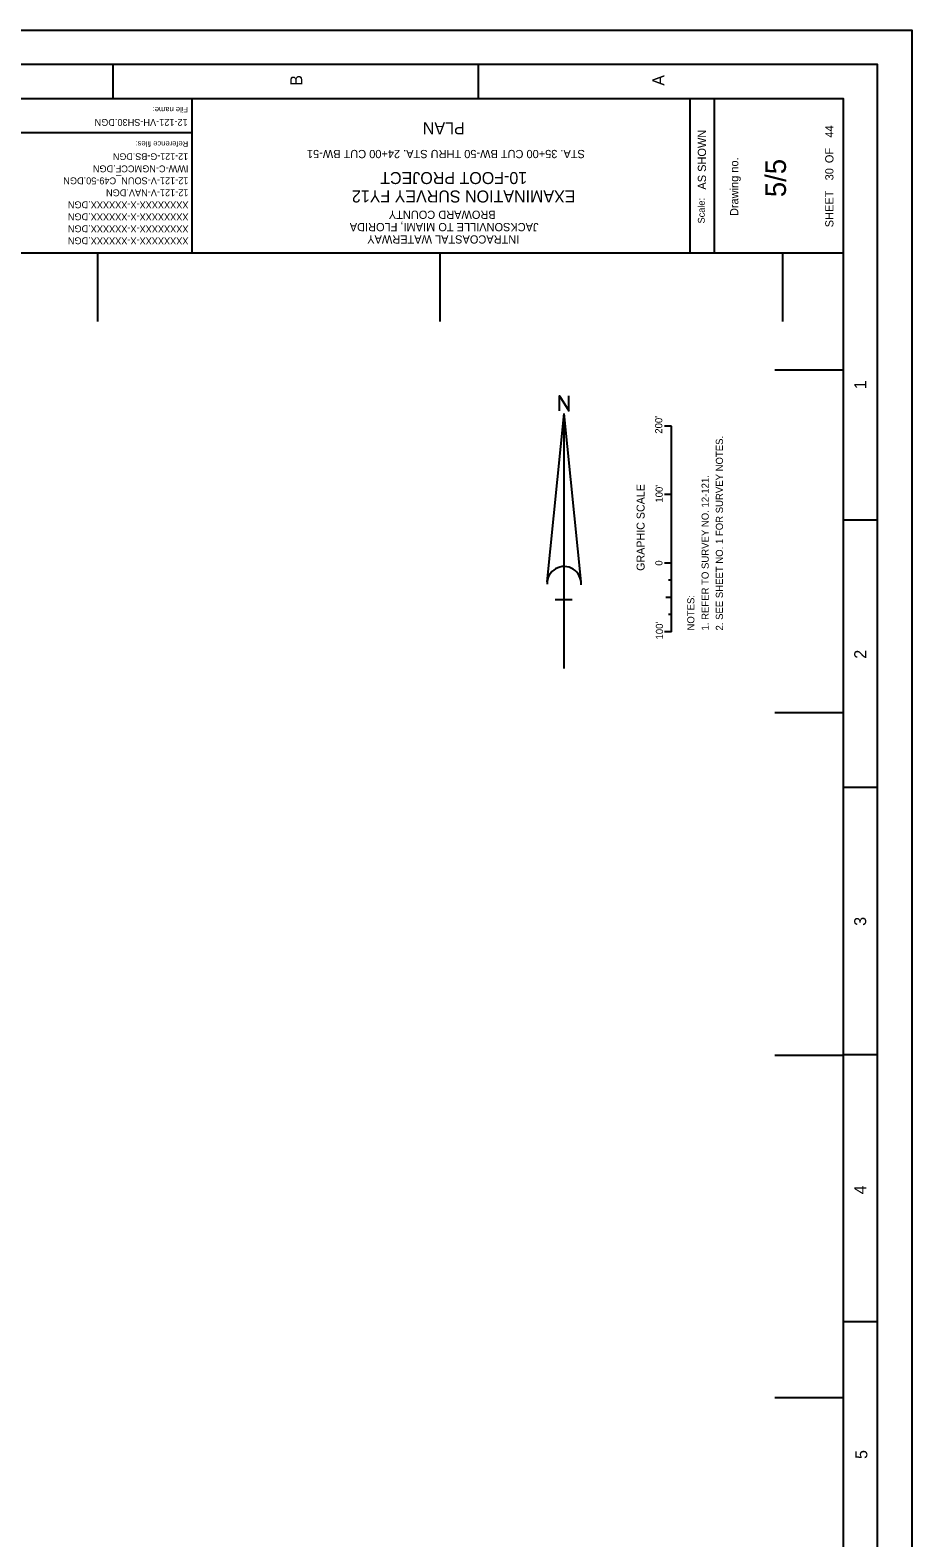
# Model space of a CAD drawing. Extents: x 945289 to 948688, y 635096 to 639496.
# Drawn here: x 947401 to 948688, y 637296 to 639496 of the extents above; entities that cross this region are included whole.
import ezdxf

# ---------------------------------------------------------------- set-up
doc = ezdxf.new("R2010")
doc.units = 0
for name, color, linetype in [('G-ANNO-NPLT', 7, 'Continuous'), ('G-ANNO-TEXT-DRWG', 7, 'Continuous'), ('G-ANNO-TEXT-PROJ', 7, 'Continuous'), ('G-ANNO-TEXT-TTLB', 7, 'Continuous'), ('G-ANNO-TTLB', 7, 'Continuous'), ('V-ANNO-NOTE', 7, 'Continuous'), ('V-ANNO-SYMB', 7, 'Continuous'), ('V-TOPO-COOR-STAT', 7, 'Continuous')]:
    doc.layers.add(name, color=color, linetype=linetype)

msp = doc.modelspace()

# ---------------------------------------------------------------- linework, layer by layer
at = {"layer": 'G-ANNO-NPLT'}
msp.add_lwpolyline([(945288.5, 635095.9), (945288.5, 639495.8), (948688.5, 639495.8), (948688.5, 635095.9)], close=True, dxfattribs=at)
msp.add_lwpolyline([(948638.5, 639496), (948688.5, 639496), (948688.5, 639446)], dxfattribs=at)
at = {"layer": 'G-ANNO-TTLB'}
for p, q in [((947521.9, 639445.8), (947521.9, 639395.8)), ((948055.2, 639445.8), (948055.2, 639395.8)), ((947637.7, 639170.8), (947637.7, 639395.8)), ((948364.7, 639170.8), (948364.7, 639395.8)), ((948400.4, 639170.8), (948400.4, 639395.8)), ((947286.3, 639346.5), (947637.7, 639346.5)), ((945388.5, 639170.8), (948588.5, 639170.8)), ((948638.5, 638780.8), (948588.5, 638780.8)), ((948638.5, 638390.8), (948588.5, 638390.8)), ((948638.5, 638000.8), (948588.5, 638000.8)), ((948638.5, 637610.9), (948588.5, 637610.9))]:
    msp.add_line(p, q, dxfattribs=at)
for points in [[(948638.5, 635145.9), (948638.5, 639445.8), (945338.5, 639445.8), (945338.5, 635145.9)], [(945388.5, 639395.8), (945388.5, 635270.9), (948588.5, 635270.9), (948588.5, 639395.8)]]:
    msp.add_lwpolyline(points, close=True, dxfattribs=at)
at = {"layer": 'V-ANNO-NOTE'}
for p, q in [((948337.8, 638918.2), (948327.3, 638918.2)), ((948337.8, 638618.2), (948337.8, 638918.2)), ((948337.8, 638818.2), (948327.3, 638818.2)), ((948337.8, 638718.2), (948327.3, 638718.2)), ((948337.8, 638718.2), (948327.3, 638718.2)), ((948337.8, 638718.2), (948332.8, 638718.2)), ((948337.8, 638693.2), (948333, 638693.2)), ((948337.8, 638668.2), (948329.3, 638668.2)), ((948337.8, 638643.2), (948333, 638643.2)), ((948337.8, 638618.2), (948327.3, 638618.2))]:
    msp.add_line(p, q, dxfattribs=at)
at = {"layer": 'V-ANNO-SYMB'}
for p, q in [((948156.1, 638690.9), (948180.8, 638936.7)), ((948180.8, 638564.3), (948180.8, 638936.7)), ((948205.5, 638690.9), (948180.8, 638936.7)), ((948192.6, 638664.9), (948167.8, 638664.9))]:
    msp.add_line(p, q, dxfattribs=at)
msp.add_lwpolyline([(948173.9, 638940.7), (948173.9, 638962.4), (948187.5, 638940.7), (948187.5, 638962.4)], dxfattribs=at)
msp.add_arc((948180.8, 638688.5), 24.8, 355.2984, 182.0673, dxfattribs=at)
at = {"layer": 'V-TOPO-COOR-STAT'}
for p, q in [((947500, 639070.8), (947500, 639170.8)), ((948000, 639070.8), (948000, 639170.8)), ((948500, 639070.8), (948500, 639170.8)), ((948588.5, 639000), (948488.5, 639000)), ((948588.5, 638500), (948488.5, 638500)), ((948588.5, 638000), (948488.5, 638000)), ((948588.5, 637500), (948488.5, 637500))]:
    msp.add_line(p, q, dxfattribs=at)

# ---------------------------------------------------------------- texts
at = {"layer": 'G-ANNO-TEXT-DRWG'}
for s, height, rotation, p in [('12-121-VH-SH30.DGN', 10, 180, (947631.3, 639366.3)), ('PLAN', 17.5, 180, (948035.7, 639361.4)), (' 30          44', 12, 90, (948574, 639272.3)), ('STA. 35+00 CUT BW-50 THRU STA. 24+00 CUT BW-51', 12, 180, (948211.1, 639321.2)), ('IWW-C-NGMCCF.DGN', 10, 180, (947632.4, 639298.6)), ('5/5', 30, 90, (948504.7, 639252.3)), ('12-121-V-SOUN_C49-50.DGN', 10, 180, (947632.4, 639281.1)), ('12-121-V-NAV.DGN', 10, 180, (947632.4, 639263.6)), ('XXXXXXXX-X-XXXXXX.DGN', 10, 180, (947632.4, 639246.1)), ('XXXXXXXX-X-XXXXXX.DGN', 10, 180, (947632.4, 639228.6)), ('XXXXXXXX-X-XXXXXX.DGN', 10, 180, (947632.4, 639211.1)), ('XXXXXXXX-X-XXXXXX.DGN', 10, 180, (947632.4, 639193.6))]:
    msp.add_text(s, height=height, rotation=rotation, dxfattribs=at).set_placement(p)
at = {"layer": 'G-ANNO-TEXT-PROJ'}
for s, height, p in [('12-121-G-BS.DGN', 9.8, (947632, 639316.3)), ('10-FOOT PROJECT', 17.5, (948126.9, 639288.9)), ('EXAMINATION SURVEY FY12', 17.5, (948197.4, 639262)), ('BROWARD COUNTY', 12, (948080.9, 639232.6)), ('JACKSONVILLE TO MIAMI, FLORIDA', 12, (948143.4, 639214.6)), ('INTRACOASTAL WATERWAY', 12, (948115.4, 639196.6))]:
    msp.add_text(s, height=height, rotation=180, dxfattribs=at).set_placement(p)
at = {"layer": 'G-ANNO-TEXT-TTLB'}
for s, height, rotation, p in [('File name:', 8, 180, (947631.7, 639383.9)), ('AS SHOWN', 12, 90, (948388, 639263.3)), ('Reference files:', 8, 180, (947631.9, 639333.9)), ('SHEET         OF', 12, 90, (948574, 639208.3)), ('Drawing no.', 12, 90, (948435.1, 639224.7)), ('Scale:', 10, 90, (948386.1, 639213.9))]:
    msp.add_text(s, height=height, rotation=rotation, dxfattribs=at).set_placement(p)
at = {"layer": 'G-ANNO-TTLB'}
for s, p in [('B', (947798.5, 639414.9)), ('A', (948327.3, 639414.9)), ('1', (948621.8, 638971.9)), ('2', (948621.8, 638578.8)), ('3', (948621.8, 638189)), ('4', (948621.8, 637797.2)), ('5', (948623.5, 637411))]:
    msp.add_text(s, height=17.5, rotation=90, dxfattribs=at).set_placement(p)
at = {"layer": 'V-ANNO-NOTE'}
for s, height, p in [("200'", 10.42, (948324.1, 638907.1)), ('2. SEE SHEET NO. 1 FOR SURVEY NOTES.', 10.416, (948412.7, 638619.9)), ('GRAPHIC SCALE', 11.666, (948298.3, 638707)), ("100'", 10.42, (948324.7, 638806.5)), ('1. REFER TO SURVEY NO. 12-121.', 10.416, (948391.9, 638619.9)), ('0', 10.4, (948324.4, 638714.5)), ('NOTES:', 10.42, (948371, 638619.9)), ("100'", 10.42, (948325.1, 638606.8))]:
    msp.add_text(s, height=height, rotation=90, dxfattribs=at).set_placement(p)

doc.saveas('drawing.dxf')
